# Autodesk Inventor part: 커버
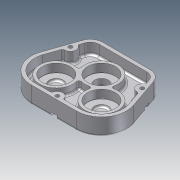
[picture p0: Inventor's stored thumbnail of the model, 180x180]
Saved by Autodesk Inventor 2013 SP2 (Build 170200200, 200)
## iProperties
Company: 한국ATC센터
Created: 2014-12
Part Number: 커버
Document SubType Name: Modeling
Designer: KYOUNG IL JANG
Density: 1 g/cm^3
Mass: 160.364 g
Surface Area: 512.085 cm^2
Volume: 160.364 cm^3
Material: 일반
Author: KYOUNG IL JANG
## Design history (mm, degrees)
sketch "스케치1"
  geometry: L1 (-66.565, -20.803)-(-47, 36); L2 (47, 36)-(66.565, -20.803); L3 (-32.527, -68.527)-(32.527, -68.527); L4 (-47, 36)-(47, 36); C1 r 28 at (0, 0); C2 r 18 at (-32.527, -32.527); C3 r 18 at (32.527, -32.527); A1 r 36 centre (-32.527, -32.527) between (-66.565, -20.803) and (-32.527, -68.527); A2 r 36 centre (32.527, -32.527) between (32.527, -68.527) and (66.565, -20.803); 2 further points
  constraints: 8 end point, 6 tangent, 5 centre point, 4 point on circle, 3 coincident, 2 equal radius, 1 equal length, 1 horizontal alignment, 1 midpoint, 1 vertical alignment
  dimensions: "d0" = 56 diameter of C1; "d1" = 36 diameter of C2; "d2" = 90 deg dimension on point (0, 0) C3.centre C2.centre; "d3" = 36 radius of A1; "d4" = 104.52691 distance between parallel lines of L3 L4 (derived); "d5" = 94 distance of L1.end L2.start; "d65" = 36 distance from line of point (0, 0) L4
extrude "돌출1" new body sketch "스케치1" distance "d6" = 25; taper "d7" = 0 deg
fillet "모깎기1" dims "d8" = 18
feature "쉘1" dims "d9" = 9, "d10" = 5
sketch "스케치2"
  geometry: C1 r 24 at (1.635, -63.527); C2 r 24 at (66.689, -63.527); C3 r 24 at (34.162, -31); 4 further points
  constraints: 4 coincident, 3 centre point, 1 equal radius
  dimensions: "d11" = 48 diameter of C3; "d12" = 48 diameter of C2
extrude "돌출2" join sketch "스케치2" distance "d13" = 11; taper "d14" = 0 deg
hole "구멍1" diameter "d17" = 20; stored, may be unused: countersink angle "d21" = 90 deg, drill point angle "d23" = 0 deg; dims "d15" = 10, "d16" = 10, "d18" = 6, "d19" = 40, "d20" = 12, "d22" = 3
hole "구멍2" diameter "d26" = 20; stored, may be unused: countersink angle "d30" = 90 deg, drill point angle "d32" = 0 deg; dims "d24" = 10, "d25" = 10, "d27" = 6, "d28" = 40, "d29" = 12, "d31" = 3
hole "구멍3" diameter "d35" = 20; stored, may be unused: countersink angle "d39" = 90 deg, drill point angle "d41" = 118 deg; dims "d33" = 10, "d34" = 10, "d36" = 6, "d37" = 40, "d38" = 12, "d40" = 3
sketch "스케치3"
  geometry: C1 r 15 at (0, 0); C2 r 20 at (0, 0); 1 further point
  constraints: 2 centre point, 2 coincident
  dimensions: "d42" = 40 diameter of C2; "d43" = 30 diameter of C1
extrude "돌출3" join sketch "스케치3" distance "d44" = 8; taper "d45" = 0 deg
feature "면 기울기1" dims angle "d46" = 10 deg
fillet "모깎기2" dims "d47" = 3
fillet "모깎기3" dims "d48" = 0.3
fillet "모깎기6" dims "d66" = 0.1
sketch "스케치4"
  geometry: L1 (-61.837, -22.432)-(-46.453, 22.233) reference; L2 (46.453, 22.233)-(61.837, -22.432) reference; L3 (32.527, -63.527)-(-32.527, -63.527) reference; L4 (-34.162, 31)-(34.162, 31) reference; A1 r 8 centre (51.7, 7) between (49.095, 14.564) and (54.305, -0.564); A2 r 8 centre (-51.7, 7) between (-54.305, -0.564) and (-49.095, 14.564); A3 r 8 centre (0, -63.527) between (8, -63.527) and (-8, -63.527)
  constraints: 8 point on line, 6 point on circle, 3 centre point, 2 equal radius, 1 horizontal alignment, 1 midpoint
  dimensions: "d49" = 8 radius of A1; "d51" = 24 distance from line of A2.centre L4
extrude "돌출4" join sketch "스케치4" stored distance "d52" = 8; taper "d53" = 0 deg
fillet "모깎기4" dims "d54" = 3
sketch "스케치5"
  geometry: A1 r 8 centre (-51.7, 7) between (-52.144, -0.988) and (-47.131, 13.567) reference; A2 r 8 centre (0, -63.527) between (7.697, -61.345) and (-7.697, -61.345) reference; A3 r 8 centre (51.7, 7) between (47.131, 13.567) and (52.144, -0.988) reference; 1 further point
hole "구멍4" sketch "스케치5" at (0, -63.527), (-51.7, 7), (51.7, 7) diameter "d55" = 5.5; stored, may be unused: countersink angle "d59" = 90 deg, drill point angle "d61" = 118 deg; dims "d56" = 6, "d57" = 9.5, "d58" = 5.4, "d60" = 3
sketch "스케치6"
  geometry: L1 (-51.181, 23.862)-(-66.565, -20.803) reference; L2 (66.565, -20.803)-(51.181, 23.862) reference; L3 (-32.527, -68.527)-(32.527, -68.527) reference; L4 (-50.153, 11.491)-(-54.881, 13.119); L5 (-53.247, 2.509)-(-57.974, 4.137); L6 (50.153, 11.491)-(54.881, 13.119); L7 (53.247, 2.509)-(57.974, 4.137); L8 (4.75, -63.527)-(4.75, -68.527); L9 (-4.75, -63.527)-(-4.75, -68.527); A1 r 4.75 centre (-51.7, 7) between (-54.994, 3.578) and (-52.188, 11.725) reference; A2 r 4.75 centre (51.7, 7) between (52.188, 11.725) and (54.994, 3.578) reference; A3 r 4.75 centre (0, -63.527) between (4.308, -65.527) and (-4.308, -65.527) reference; 1 further point
  constraints: 12 end point, 6 perpendicular, 6 point on circle, 6 point on line, 6 tangent
extrude "돌출5" cut sketch "스케치6" distance "d62" = 5.4; taper "d63" = 0 deg
fillet "모깎기5" dims "d64" = 3
node "솔리드1"
